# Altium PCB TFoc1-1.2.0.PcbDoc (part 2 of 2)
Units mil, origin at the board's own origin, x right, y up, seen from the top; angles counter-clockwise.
Board outline 1584.83 x 1584.83 mil, 4 copper layers (Top Layer, GND, SIGNAL, Bottom Layer), stack 61.85 mil thick; 89 components, 88 nets, 364 pads, 205 vias.
Unrouted connection lines stored in the file: 1.
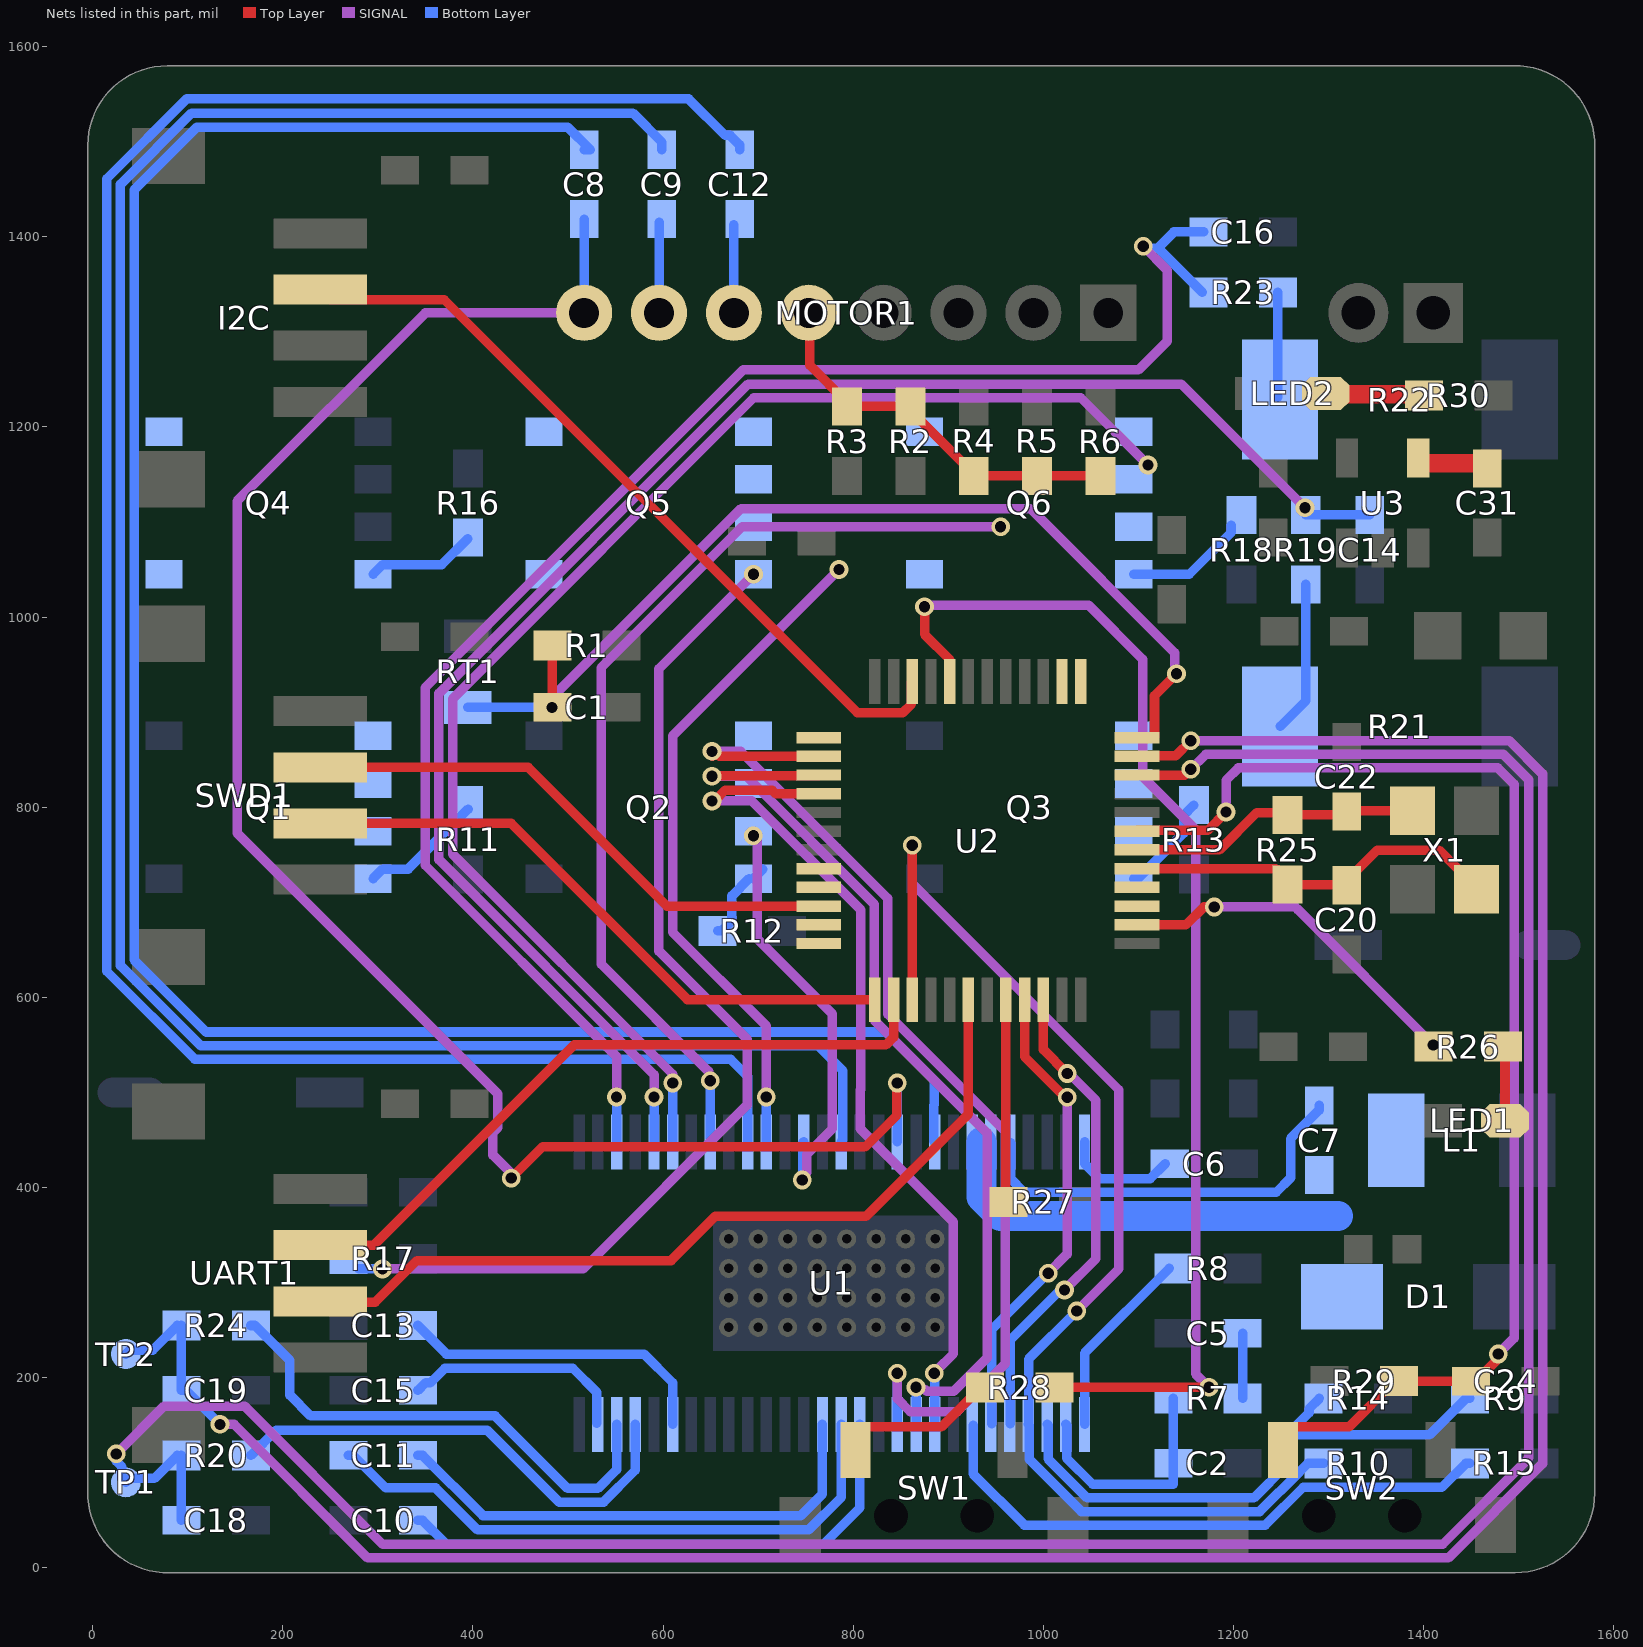
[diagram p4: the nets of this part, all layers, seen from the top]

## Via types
v1: diameter 19.68, hole 11.81, Top Layer to Bottom Layer, tented both sides, 205 vias

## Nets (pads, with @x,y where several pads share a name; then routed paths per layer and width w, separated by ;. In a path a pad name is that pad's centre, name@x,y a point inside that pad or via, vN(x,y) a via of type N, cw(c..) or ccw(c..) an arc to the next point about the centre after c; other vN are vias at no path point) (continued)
I2C_SDA: I2C.2 U2.22 | length 832.7
  Top Layer w10: I2C.2@239.45,1344.53 250.2,1333.78 369.9,1333.78 804.19,899.49 852.29,899.49 861.11,908.31 U2.22@861.11,931.32
M_A: C8.1 MOTOR1.8 Q1.S Q4.D U1.46 | length 1902.9
  Top Layer w10: v1(440.31,410) 473.31,443 812.73,443 845.89,476.15 845.89,509.49 v1(846.4,510)
  SIGNAL w10: v1@440,415.42 421.14,434.28 421.14,457.94 425.98,462.78 425.98,498.86 152.01,772.83 152.01,1122.01 350,1320 MOTOR1.8@515.37,1320
  Bottom Layer w10: MOTOR1.8@517.01,1320 517.01,1418.23 C8.1@517.27,1418.5 ; U1.46@846.4,448 v1(846.4,510)
M_B: C9.1 MOTOR1.7 Q2.S Q5.D U1.41 | length 542.8
  SIGNAL w10: v1(695,770) 699.25,765.75 699.25,661.55 778.02,582.78 778.02,461.89 751.13,435 751.13,415.42 747.52,411.81 v1@747.52,409.19
  Bottom Layer w10: MOTOR1.7@595.75,1320 C9.1@595.75,1415.4 ; v1@747.13,408.8 747.13,447.16 U1.41@747.97,448
  other v1: 746.28,407.95
M_B_Current: Q5.S R19.1 R21.2 U1.39 | length 875.9
  SIGNAL w10: v1(708.6,495.29) 708.6,570 610,668.6 610,875 v1(785,1050)
  Bottom Layer w10: U1.39@708.6,448 v1(708.6,495.29) ; R21.2@1249.02,885 1275.92,911.9 R19.1@1275.92,1034.44
M_C: C12.1 MOTOR1.6 Q3.S Q6.D U1.36 | length 1120.3
  SIGNAL w10: v1(649.55,512.29) 647.87,513.97 647.87,522.13 535,635 535,946.87 683.13,1095 v1(955,1095)
  Bottom Layer w10: U1.36@649.55,448 v1(649.55,512.29) ; MOTOR1.6@674.49,1320 C12.1@674.49,1412.58
M_C_Current: Q6.S R22.2 R23.1 U1.34 | length 1563.8
  SIGNAL w10: v1(610.18,510) 610.18,519.29 378.63,750.84 378.63,913.9 695.4,1230.67 1039.33,1230.67 v1(1110,1160)
  Bottom Layer w10: U1.34@610.18,448 v1(610.18,510) ; R22.2@1246.52,1231.29 R23.1@1246.52,1341.39
MSPI_SCLK: U1.11 U2.26 | length 1125
  Top Layer w10: v1@651.42,854.17 v1@651.71,853.88 ; v1(651.42,858.79) 654.04,858.79 659.25,853.58 U2.26@763.1,853.58 ; U2.26@763.39,853.88 U2.26@763.69,853.58
  SIGNAL w10: v1(651.42,858.79) 681.74,858.79 836.33,704.2 836.33,582.41 960,458.74 960,215 909.33,164.33 860,164.33 846.4,177.93 v1(846.4,204.81)
  Bottom Layer w10: U1.11@846.4,151 v1(846.4,204.81)
MSPI_SDI: U1.9 U2.28 | length 908.5
  Top Layer w10: v1@652.98,805.55 654.6,803.92 v1@655.89,803.92 ; v1@654.6,807.26 665.18,817.83 714.81,817.83 718.44,814.21 U2.28@763.69,814.21
  SIGNAL w10: v1(651.42,806.69) 693.31,806.69 807.67,692.33 807.67,503.07 807.54,502.94 807.54,461.79 905.33,364 905.33,225.33 v1@887.58,207.58
  Bottom Layer w10: v1(885.26,204.81) 885.51,204.56 U1.9@885.51,151.26
MSPI_SDO: U1.10 U2.27 | length 996.2
  Top Layer w10: v1@651.42,830.16 652.01,829.57 v1@654.63,829.57 ; v1(651.42,832.74) 652,833.32 U2.27@763.11,833.32
  SIGNAL w10: v1(651.42,832.74) 687.53,832.74 822,698.27 822,576.47 940.85,457.62 940.85,220.85 905.64,185.64 877.31,185.64 874.81,188.15 867.94,188.15 v1@867.67,188.41
  Bottom Layer w10: U1.10@866.08,151 v1(866.08,190)
NetC2_1: C2.1 R7.1 U1.2 | length 249.8
  Bottom Layer w10: U1.2@1023.56,151 1024.56,150 1024.56,115.31 1051.88,87.99 1136.59,87.99 C2.1@1136.59,110 R7.1@1136.59,178.33
NetC5_1: C5.1 R7.2 | length 68.3
  Bottom Layer w10: R7.2@1209.59,178.33 C5.1@1209.59,246.67
NetC6_2: C6.2 U1.56 | length 120.4
  Bottom Layer w10: U1.56@1043.25,448 1043.25,425.22 1058.98,409.49 1112.38,409.49 C6.2@1127.89,425
NetC7_1: C7.1 D1.2 L1.1 U1.50 U1.51 | length 441.3
  Bottom Layer w31.5: 935,448 935,390 955,370 1310,370
NetC7_2: C7.2 U1.52 | length 432.9
  Bottom Layer w10: U1.52@965.51,447 965.51,409.49 979.92,395.08 1244.83,395.08 1260,410.25 1260,451.5 1290,481.5 C7.2@1290,486.5
NetC8_2: C8.2 U1.48 | length 2292.1
  Bottom Layer w10: C8.2@517.27,1491.5 523.5,1491.5 500,1515 109.49,1515 43.66,1449.17 43.66,639.49 119.49,563.66 834.22,563.66 885.26,512.63 885.26,487.06 884.77,486.57 884.77,449 U1.48@885.77,448
NetC9_2: C9.2 U1.43 | length 2324
  Bottom Layer w10: C9.2@598.84,1491.5 598.84,1499.43 568.28,1530 104.22,1530 29.33,1455.11 29.33,633.55 113.55,549.33 762.78,549.33 789.17,522.94 789.17,449.83 U1.43@787.34,448
NetC10_1: C10.1 U1.13 | length 578.7
  Bottom Layer w10: C10.1@342.18,50 347.18,50 372.18,25 768.68,25 807.03,63.35 U1.13@807.03,151
NetC11_1: C11.1 U1.14 | length 641.6
  Bottom Layer w10: C11.1@269.18,118.33 274.18,118.33 308.34,84.17 360.83,84.17 405,40 753.11,40 787.34,74.23 U1.14@787.34,151
NetC11_2: C11.2 U1.15 | length 534.4
  Bottom Layer w10: C11.2@342.18,118.33 347.18,118.33 410.51,55 745,55 767.66,77.66 U1.15@767.66,151
NetC12_2: C12.2 U1.38 | length 2347.5
  Bottom Layer w10: C12.2@680.41,1491.5 680.41,1496.5 670.41,1506.5 665.41,1506.5 626.91,1545 98.95,1545 15,1461.05 15,627.62 107.62,535 671,535 688.92,517.08 U1.38@688.92,448
NetC13_2: C13.2 U1.23 | length 336.8
  Bottom Layer w10: C13.2@342.18,255 372.18,225 580,225 610.18,194.82 U1.23@610.18,151
NetC14_2: C14.2 R19.2 U1.33 | length 1732.3
  SIGNAL w10: v1(590.49,495.29) 590.49,518.71 364.3,744.9 364.3,919.83 689.47,1245 1145,1245 v1(1275,1115)
  Bottom Layer w10: U1.33@590.49,448 v1(590.49,495.29) ; R19.2@1275.92,1107.44 C14.2@1343.42,1107.44
NetC15_1: C15.1 U1.27 | length 241
  Bottom Layer w10: C15.1@342.18,186.67 350.33,194.82 355.33,194.82 370.51,210 505,210 530.44,184.56 U1.27@530.44,152
NetC16_2: C16.2 R23.2 U1.31 | length 1739.7
  SIGNAL w10: v1(551.12,495.29) 551.12,537.81 349.97,738.96 349.97,925.77 684.2,1260 1100,1260 1130,1290 1130,1365 v1(1105,1390)
  Bottom Layer w10: U1.31@551.12,448 v1(551.12,495.29) ; v1(1105,1390) 1106.85,1388.15 1120.47,1388.15 ; R23.2@1167.23,1341.39 1120.47,1388.15 ; C16.2@1168.52,1405 1137.32,1405 1120.47,1388.15
NetC31_1: C31.1 U3.4 | length 69.6
  Top Layer w19.68: U3.4@1399.47,1161.87 1461.54,1161.87 1466.69,1156.71 C31.1@1466.69,1156.5
NetLED1_2: LED1.2 R26.2 | length 72.7
  Top Layer w10: LED1.2@1485.44,480.26 R26.2@1485.44,553
NetLED2_2: LED2.2 R30.1 | length 102.9
  Top Layer w19.68: LED2.2@1296.7,1235.26 1297.7,1234.26 R30.1@1399.19,1234.26
NetMOTOR1_5: MOTOR1.5 R2.2 R3.2 R4.1 R5.1 R6.1 | length 417.2
  Top Layer w10: MOTOR1.5@754.27,1318.96 754.27,1265 793.52,1225.75 R3.2@793.52,1221.5 R2.2@860.14,1221.5 860.14,1217.25 913.89,1163.5 916.01,1163.5 R4.1@931.01,1148.5 ; R4.1@926.76,1148.5 R4.1@931.01,1148.5 ; R6.1@1060,1148.5 R5.1@993.38,1148.5 R4.1@931.01,1148.5
NetQ1_G: Q1.G R11.1 | length 130.3
  Bottom Layer w10: Q1.G@295.04,725 305.04,735 331.87,735 R11.1@395,798.13
NetQ2_G: Q2.G R12.1 | length 85.4
  Bottom Layer w10: R12.1@657.35,670 661.6,670 672.35,680.75 672.35,706.81 Q2.G@690.54,725 ; Q2.G@695.04,725 Q2.G@705.04,735
NetQ3_G: Q3.G R13.1 | length 106
  Bottom Layer w10: Q3.G@1095.04,725 1099.54,725 1147.39,772.85 1147.39,791.47 R13.1@1158.14,802.22
NetQ4_G: Q4.G R16.1 | length 115.3
  Bottom Layer w10: Q4.G@295.04,1045 305.04,1055 367.12,1055 R16.1@394.72,1082.6
NetQ5_G: Q5.G R17.1 | length 1117.7
  SIGNAL w10: v1(305,314.43) 516.01,314.43 688.29,486.71 688.29,556.18 595.67,648.8 595.67,945.63 v1(695.04,1045)
  Bottom Layer w10: R17.1@279.74,314.43 v1(305,314.43)
NetQ6_G: Q6.G R18.1 | length 128.4
  Bottom Layer w10: Q6.G@1095.04,1045 1153.38,1045 1197.67,1089.29 R18.1@1197.67,1096.69
NetR8_2: R8.2 U1.1 | length 200.9
  Bottom Layer w10: U1.1@1043.25,151 1043.25,225.91 R8.2@1132.33,315
NetR9_2: R9.2 R14.1 U1.3 | length 611.6
  Bottom Layer w10: U1.3@1003.88,151 1004.88,150 1004.88,114.73 1045.95,73.66 1221.44,73.66 1255.34,107.55 1255.34,139.1 1256.23,140 ; R14.1@1290.31,178.33 1279.57,167.59 1279.57,163.33 1256.23,140 ; R9.2@1448.5,178.33 1444.25,178.33 1405.91,140 1256.23,140
NetR15_2: R15.2 U1.7 | length 622.7
  Bottom Layer w10: U1.7@926.14,150 926.14,98.86 980,45 1233.31,45 1273.24,84.92 1419.17,84.92 1444.25,110 R15.2@1448.5,110
NetR20_2: R20.2 U1.25 | length 508.8
  Bottom Layer w10: R20.2@166.5,118.33 193.17,145 415,145 490.67,69.33 537.38,69.33 570.81,102.76 U1.25@570.81,151
NetR24_2: R24.2 U1.26 | length 532.7
  Bottom Layer w10: R24.2@166.5,255 170.75,255 207.52,218.23 207.52,181.83 229.35,160 423.33,160 499.67,83.66 531.44,83.66 551.12,103.34 U1.26@551.12,151
NetR27_2: R27.2 U2.44 | length 209.7
  Top Layer w10: R27.2@960.54,387.96 960.54,525 U2.44@960.54,597.68
NetR28_1: R28.1 SW1.2 | length 167.4
  Top Layer w10: SW1.2@802.32,123.9 802.32,137.68 813.07,148.43 892.67,148.43 R28.1@934.25,190
NetU2_3: U2.3
NetU2_4: U2.4
NetU2_13: U2.13
NetU2_14: U2.14
NetU2_25: U2.25
NetU2_32: U2.32
NetU2_33: U2.33
NetU2_35: U2.35
NetU2_36: U2.36
nFAULT: U1.6 U2.45 | length 498.4
  Top Layer w10: U2.45@980.22,597.68 980.22,537.66 1022.89,495 v1(1025,495)
  SIGNAL w10: v1(1005,310) 1025,330 v1(1025,495)
  Bottom Layer w10: U1.6@945.72,151.89 945.72,250.72 v1(1005,310)
nOCTW: U1.5 U2.46 | length 508
  Top Layer w10: U2.46@999.91,597.68 999.91,545.09 v1(1025,520)
  SIGNAL w10: v1(1022.25,292.25) 1055,325 1055,492.11 v1@1027.11,520
  Bottom Layer w10: U1.5@965.01,151.5 965.01,239.5 1017.75,292.25 v1(1022.25,292.25)
NRST: C24.2 R29.1 SW2.2 U2.7 | length 1331.8
  Top Layer w10: U2.7@1098.33,774.84 1099.33,775.84 1172.91,775.84 v1(1192.07,795) ; SW2.2@1252.05,123.9 1252.05,137.68 1262.8,148.43 1321.51,148.43 R29.1@1369.5,196.42 ; R29.1@1373.76,196.42 C24.2@1449.69,196.42 1454.69,196.42 1476.42,218.15 1476.42,223.15 v1(1478.27,225)
  SIGNAL w10: v1(1192.07,795) 1192.07,828.43 1204.98,841.34 1477.82,841.34 1495,824.16 1495,241.73 v1(1478.27,225)
OSC_IN: C20.1 R25.1 U2.5 X1.3 | length 406.8
  Top Layer w10: U2.5@1098.33,735.47 1244.57,735.47 1251.5,728.54 R25.1@1251.5,713.66 ; R25.1@1256.82,718.5 C20.1@1314.56,718.5 ; C20.1@1318.56,718.5 C20.1@1314.56,718.5 ; X1.3@1455.28,713.66 1455.28,715.63 1415.91,755 1351.06,755 C20.1@1314.56,718.5
OSC_OUT: C22.1 R25.2 U2.6 X1.1 | length 308.3
  Top Layer w10: U2.6@1099.33,756.16 1100.33,755.16 1185.16,755.16 1224.17,794.17 1254.61,794.17 R25.2@1256.82,791.97 1315.53,791.97 C22.1@1319.06,795.51 1319.89,796.34 X1.1@1388.35,796.34
PB2: R28.2 U2.20 | length 1300.2
  Top Layer w10: v1(875,1011) 875,981.81 901.48,955.33 U2.20@901.48,932.32 ; R28.2@1011.5,190 v1(1174.17,190)
  SIGNAL w10: v1(875,1011) 876.24,1012.24 1047.76,1012.24 1104.33,955.67 1104.33,832.36 1160,776.69 1160,204.17 v1(1174.17,190)
PC13: R26.1 U2.2 | length 379.6
  Top Layer w10: U2.2@1098.33,676.42 1149.92,676.42 1168.71,695.21 v1(1179.64,695.21)
  SIGNAL w10: v1(1179.64,695.21) 1264.79,695.21 1267.67,692.33 v1(1410,550)
PWRGD: R10.2 U1.4 U2.39 | length 1290.8
  Top Layer w10: U2.39@862.11,597.68 v1(862.11,760)
  SIGNAL w10: v1(862.11,760) 862.11,720 1079.17,502.94 1079.17,314.43 v1(1035,270.26)
  Bottom Layer w10: U1.4@984.19,151 985.19,150 985.19,114.15 1040.01,59.33 1227.38,59.33 1269.67,101.62 1269.67,101.71 1277.95,110 R10.2@1294.57,110 ; U1.4@984.33,151.14 984.33,219.6 v1(1035,270.26)
SO1: C18.1 R20.1 TP1.1 U2.10 | length 2912.4
  Top Layer w10: U2.10@1098.33,833.9 1148.9,833.9 v1(1155,840)
  SIGNAL w10: v1(25,120) 75.17,170.17 159.83,170.17 305,25 1420,25 1510.67,115.67 1510.67,828.76 1483.76,855.67 1170.67,855.67 v1(1155,840)
  Bottom Layer w10: v1(25,120) 25,112.38 30.89,106.49 TP1.1@30.89,94.11 ; TP1.1@35,90 39.11,94.11 65.03,94.11 R20.1@89.25,118.33 ; C18.1@93.5,50 R20.1@93.5,118.33
SO2: C19.1 R24.1 TP2.1 U2.11 | length 2853.8
  Top Layer w10: U2.11@1098.33,853.58 1099.04,854.29 1139.29,854.29 v1(1155,870)
  SIGNAL w10: v1(133.96,151) 149,151 289.33,10.67 1425.94,10.67 1525,109.73 1525,835 1490,870 v1(1155,870)
  Bottom Layer w10: TP2.1@35,225 39.11,229.11 63.36,229.11 R24.1@89.25,255 ; R24.1@93.5,255 C19.1@93.5,186.67 98.5,186.67 133.96,151.2 v1(133.96,151)
SWDCLK: SWD1.3 U2.37 | length 660
  Top Layer w10: SWD1.3@239.45,782.97 440.31,782.97 625.6,597.68 U2.37@822.74,597.68
SWDIO: SWD1.2 U2.34 | length 584.7
  Top Layer w10: SWD1.2@239.45,842.03 457.97,842.03 603.9,696.1 U2.34@763.69,696.1
TEMP: C1.1 R1.1 RT1.1 U2.12 | length 1078.8
  Top Layer w10: C1.1@483.5,905 R1.1@483.5,970 ; U2.12@1098.33,873.27 1115.83,873.27 1116.83,874.27 1116.83,917.31 v1(1140,940.47)
  SIGNAL w10: v1@484.93,906.79 484.93,917.06 682.03,1114.17 986.36,1114.17 1138.15,962.39 1138.15,942.33 v1(1140,940.47)
  Bottom Layer w10: RT1.1@394.75,904.94 v1(483.07,904.94)
USART1_RX: U2.38 UART1.2 | length 733.1
  Top Layer w10: UART1.2@239.45,339.53 295.97,339.53 506.44,550 834.33,550 842.43,558.1 U2.38@842.43,597.68
USART1_TX: U2.42 UART1.3 | length 884.5
  Top Layer w10: UART1.3@239.45,280.47 240.45,279.47 297.15,279.47 341.03,323.35 608.35,323.35 655,370 813.89,370 921.17,477.28 U2.42@921.17,597.68
pads on no net: I2C.0 SW1.0 SW2.0 SWD1.0 U1.55 U1.V UART1.0 X1.2 X1.4
copper on no net: | length 62
  Bottom Layer w15: 681,358 712,358 743,358

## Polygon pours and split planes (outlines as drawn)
DGND on Top Layer "DGND_L01_P000" (solid, remove dead copper, pour order 0): 1500,1570 cw(c1500,1500) 1570,1500 1570,80 cw(c1495,80) 1495,5 80,5 cw(c80,80) 5,80 5,1500 cw(c75,1500) 75,1570
DGND on SIGNAL "DGND_L03_P006" (solid, remove dead copper, pour order 6): 1485,1575 cw(c1485,1485) 1575,1485 1575,90 cw(c1485,90) 1485,0 99.14,0 cw(c99.14,94.14) 5,94.14 5,1500 cw(c80,1500) 80,1575
DCBUS on Bottom Layer "DCBUS_L04_P010" (solid, remove dead copper, pour order 10): 59.18,740 59.18,648.8 135.75,572.22 301.72,572.22 305.73,640.06 302.8,642.98 275.79,670 245.99,670 245.99,701.24 235.45,711.78 235.45,740
DCBUS on Bottom Layer "DCBUS_L04_P008" (solid, remove dead copper, pour order 8): 457.28,740 621.24,740 621.24,600 616.24,605 455,605
GND on GND (split plane): 1560.63,1549.94 1563.18,1546.25 1560.32,1549.98 1557.39,1553.18
GND on GND (split plane): 1569.24,1537.51 1571.03,1533.54 1568.71,1538.01 1566.59,1541.33
GND on GND (split plane): 1549.94,1560.63 1553.18,1557.39 1549.98,1560.32 1546.25,1563.18
GND on GND (split plane): 1579.15,1509.06 1579.41,1505.03 1578.67,1510.63 1578.04,1513.51
GND on GND (split plane): 1575.48,1523.73 1576.5,1519.65 1574.89,1524.75 1573.55,1527.98
GND on GND (split plane): 1509.07,1579.15 1513.51,1578.04 1510.63,1578.67 1505.03,1579.41
GND on GND (split plane): 71.43,1579.63 65.84,1578.89 70.49,1579.82 75.77,1579.82
GND on GND (split plane): 1537.51,1569.24 1541.33,1566.59 1538.01,1568.71 1533.54,1571.03
GND on GND (split plane): 1523.73,1575.48 1527.98,1573.55 1524.75,1574.89 1519.65,1576.5
GND on GND (split plane): 1579.82,70.49 1578.89,65.84 1579.63,71.43 1579.82,75.77
GND on GND (split plane): 1576.6,54.31 1575.06,50.6 1577.09,57.03 1577.58,59.26
GND on GND (split plane): 1570.29,39.07 1567.48,34.87 1568.71,36.8 1571.82,42.78
GND on GND (split plane): 1561.12,25.35 1557.39,21.62 1560.32,24.82 1563.75,29.29
GND on GND (split plane): 1549.45,13.68 1545.51,11.05 1549.98,14.48 1553.18,17.41
GND on GND (split plane): 1535.74,4.52 1532.02,2.98 1538.01,6.09 1539.93,7.32
GND on GND (split plane): 1520.49,-1.8 1515.54,-2.78 1517.77,-2.29 1524.21,-0.26
GND on GND (split plane): 1504.31,-5.01 1499.04,-5.01 1503.37,-4.83 1508.96,-4.09
GND on GND (split plane): 57.03,1577.09 50.6,1575.06 54.31,1576.6 59.26,1577.58
GND on GND (split plane): 36.8,1568.71 34.87,1567.48 39.07,1570.29 42.78,1571.82
GND on GND (split plane): 24.82,1560.32 21.62,1557.39 25.35,1561.12 29.29,1563.76
GND on GND (split plane): 14.48,1549.98 11.05,1545.51 13.68,1549.45 17.41,1553.19
GND on GND (split plane): 6.09,1538.01 2.98,1532.02 4.52,1535.74 7.32,1539.93
GND on GND (split plane): -2.29,1517.77 -2.78,1515.54 -1.8,1520.49 -0.26,1524.21
GND on GND (split plane): -3.87,64.17 -3.36,61.85 -4.42,66.19 -4.65,70.1
GND on GND (split plane): -4.83,1503.37 -5.02,1499.04 -5.02,1504.31 -4.09,1508.96
GND on GND (split plane): 36.8,6.09 41.42,3.68 37.46,5.46 33.57,8.15
GND on GND (split plane): 78.77,1579.76 1500.2,1579.76 1501.48,1579.51 1501.51,1579.59 1501.52,1579.59 1501.51,1579.51 1503.36,1579.43 1510.59,1578.48 1517.72,1576.9 1524.68,1574.7 1531.43,1571.91 1537.91,1568.54 1544.06,1564.61 1549.85,1560.17 1555.24,1555.24 1560.17,1549.85 1564.61,1544.06 1568.54,1537.91 1571.91,1531.43 1574.7,1524.68 1576.9,1517.72 1578.48,1510.59 1579.43,1503.36 1579.51,1501.51 1579.59,1501.52 1579.59,1501.51 1579.51,1501.48 1579.76,1500.2 1579.76,78.74 1579.75,78.74 1579.43,71.45 1578.48,64.21 1576.9,57.08 1574.7,50.12 1571.91,43.37 1568.54,36.9 1564.61,30.74 1560.17,24.95 1555.24,19.57 1549.85,14.63 1544.06,10.19 1537.91,6.27 1531.43,2.9 1524.68,0.1 1517.72,-2.09 1510.59,-3.67 1503.36,-4.63 1496.06,-4.94 1496.06,-4.96 75,-4.96 73.83,-4.73 73.81,-4.82 73.8,-4.82 73.81,-4.73 71.45,-4.63 64.21,-3.67 57.08,-2.09 50.12,0.1 43.37,2.9 36.9,6.27 30.74,10.19 24.95,14.63 19.57,19.57 14.63,24.95 10.19,30.74 6.27,36.9 2.9,43.37 0.1,50.12 -2.09,57.08 -3.67,64.21 -4.63,71.45 -4.73,73.81 -4.82,73.8 -4.82,73.81 -4.73,73.83 -4.96,75 -4.96,1496.06 -4.94,1496.06 -4.63,1503.36 -3.67,1510.59 -2.09,1517.72 0.1,1524.68 2.9,1531.43 6.27,1537.91 10.19,1544.06 14.63,1549.85 19.57,1555.24 24.95,1560.17 30.74,1564.61 36.9,1568.54 43.37,1571.91 50.12,1574.7 57.08,1576.9 64.21,1578.48 71.45,1579.43 78.74,1579.75 78.74,1579.76 78.77,1579.76
GND on GND (split plane): 64.17,-3.87 70.1,-4.65 66.19,-4.42 61.85,-3.36
GND on GND (split plane): 50.05,-0.09 55.4,-1.77 51.38,-0.78 47.09,1.14
GND on GND (split plane): 6.09,36.8 8.15,33.57 5.46,37.46 3.68,41.42
GND on GND (split plane): -0.09,50.05 1.14,47.09 -0.79,51.38 -1.77,55.4
GND on GND (split plane): 24.82,14.48 28.63,11.56 24.91,14.12 21.62,17.41
GND on GND (split plane): 14.48,24.82 17.41,21.62 14.12,24.91 11.56,28.63

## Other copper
SIGNAL:
  region net DCBUS: 905.33,720 1050.94,565 ccw(c1056.97,571.04) 1056.97,562.5 1085,562.5 ccw(c1085,567.5) 1090,567.5 1090,600 945,760 ccw(c940.92,755.92) 940.92,761.69 909.41,761.69 ccw(c909.41,755.92) 905.33,760 ccw(c913.45,751.88) 901.97,751.88 901.97,728.12 ccw(c913.45,728.12)
  region net DCBUS: 225,455 185.85,455 cw(c185.85,465.85) 175,465.85 175,510 80,715 80,767.17 cw(c92.83,767.17) 92.83,780 120,780 cw(c120,770) 130,770 130,727.56 225,510
  region: 225,455.96
Bottom Layer:
  rectangle net DCBUS: 81.15,711.25 180,785
  rectangle net GND: 248.91,1078.45 349.61,1211.49
  rectangle net NetC7_1: 920,420 950,475
  region net GND: 1460,821.32 1460,1365 ccw(c1436.85,1365) 1436.85,1388.15 1388.15,1388.15 ccw(c1388.15,1360) 1360,1360 1363.89,1308.62 cw(c1337.2,1315.82) 1330,1289.13 cw(c1323.62,1325.75) 1287.14,1318.63 1283.12,1455.16 cw(c1341.78,1456.89) 1350,1515 1460,1515 cw(c1460,1430) 1545,1430 1545,826.32 cw(c1540,826.32) 1540,821.32
  region net DCBUS: 175,520 174.3,519.3 174.3,460 ccw(c179.3,460) 179.3,455 265,455 ccw(c265,475) 285,475 285,515 ccw(c280,515) 280,520
  region net M_C: 906.46,1030.07 ccw(c1021.52,1030.07) 1021.52,915 cw(c1021.52,881.52) 1055,881.52 ccw(c1063.98,881.52) 1063.98,872.54 1106.85,872.54 ccw(c1106.85,879.12) 1113.43,879.12 1113.43,961.52 ccw(c1068.97,961.52) 1068.97,1005.98 1060.23,1005.98 cw(c1060.23,1028.99) 1037.23,1028.99 1037.23,1030
  region net M_B_Current: 675.74,1210 675.74,1080.2 719.26,1080.2 cw(c719.54,1037.74) 762,1038 762,691 ccw(c808,691) 808,645 875,645 cw(c875.01,615.09) 886.46,642.72 ccw(c953.53,710.02) 953.52,615 1187.03,615 ccw(c1187.03,717.42) 1289.45,717.42 1289.45,925.22 ccw(c1269.67,925.22) 1269.67,945 1246.4,945 ccw(c1241.94,913.4) 1210.34,917.84 1208.04,729.39 cw(c1162.38,720.67) 1171.08,675 1010,675 927.5,705 856.4,705 cw(c856.4,715) 846.4,715 846.4,1147.6 ccw(c824,1147.61) 824,1170 774.2,1170 cw(c774.2,1190) 754.2,1190 ccw(c734.21,1190) 734.2,1210
  region net NetC7_1: 1271.99,250 1355,250 1355,325 cw(c1375,325) 1375,345 ccw(c1375,370) 1400,370 1400,405 ccw(c1370,405) 1370,435 1283.97,435 ccw(c1283.97,423.02) 1271.99,423.02
  region net M_C: 672.52,1349.45 cw(c672.56,1322.01) 700,1322.05 700,1308.62 ccw(c770.91,1379.54) 770.91,1279.25 967.98,1279.25 cw(c967.98,1210) 1037.23,1210 cw(c1008.19,1210) 1008.19,1180.97 840.46,1180.97 cw(c840.45,1280.96) 778.22,1202.69 ccw(c725.98,1126.4) 708.95,1217.28 cw(c717.35,1292.11) 645,1271.24 645,1321.93 cw(c672.52,1321.93)
  region net M_C_Current: 1075,1213.51 cw(c1085,1213.51) 1085,1223.51 1108.44,1223.51 ccw(c1108.44,1283.57) 1168.5,1283.57 cw(c1176.36,1283.57) 1176.36,1291.43 1243.5,1291.43 cw(c1243.5,1274.93) 1260,1274.93 1260,1189.47 cw(c1237.03,1189.47) 1237.03,1166.5 1210,1166.5 ccw(c1210,1126.5) 1170,1126.5 1168.5,1075 cw(c1162.22,1076.28) 1160.94,1070 1142.94,1070 1105,1070 cw(c1102.31,1111.31) 1075,1080.2 cw(c1086.83,1085.1) 1075,1090
  region net M_B: 456.1,1034.95 ccw(c555.08,1032.52) 552.65,933.54 593.69,933.54 cw(c593.69,860.08) 667.15,860.08 667.15,765.72 ccw(c677.87,765.72) 677.87,755 746.65,755 ccw(c746.65,762.55) 754.2,762.55 754.2,880.89 ccw(c654.2,880.89) 695.06,972.16 cw(c695.06,1030) 637.23,1030
  region net M_A: 330.05,760 330.05,904.94 ccw(c216.1,916.77) 301.72,992.89 242.26,1017.44 cw(c269.19,1037.18) 235.8,1037.18 ccw(c218.52,1030.03) 231.73,1043.27 225,1050 ccw(c200.87,1025.88) 200.86,1060 67.07,1060 ccw(c67.06,1042.95) 55,1055 55,1003.5 ccw(c109.86,1003.5) 71.07,964.71 86.84,948.94 ccw(c147.63,1009.73) 147.63,923.76 206.91,923.76 cw(c206.92,859.73) 252.19,905 cw(c197.15,849.95) 275,849.94 275,760
  region net M_B: 593.78,1350 cw(c594.39,1319.39) 625,1319.97 630.82,1244.92 cw(c580.54,1217.22) 637.23,1226.27 637.23,1210 cw(c577.23,1210) 577.23,1150 485,1150 cw(c485,1180) 455,1180 455,1210 cw(c470,1210) 470,1225 520,1225 ccw(c517.5,1267.5) 560,1270 565,1321.22 cw(c593.78,1321.22)
  region net M_A: 79.23,1200 79.23,1250.06 cw(c179.23,1250.06) 179.23,1350.06 520,1350.06 cw(c520.04,1323.71) 546.39,1323.61 546.39,1320 cw(c469.2,1320) 469.2,1242.8 270.03,1242.8 ccw(c270.03,1210) 238.79,1200
  region net M_C: 1114.33,890 1114.33,765.89 cw(c1108.44,765.89) 1108.44,760 1060.66,760 cw(c1060.66,765.66) 1055,765.66 1055,881.52 cw(c1063.48,881.52) 1063.48,890
  region: 248.91,1211.49
  region net M_C: 930.28,1030.07
  region: 980,505
  region net M_A: 275,760
  region: 557.53,1445.74

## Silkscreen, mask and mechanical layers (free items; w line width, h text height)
Top Overlay:
  lines w10: 1175,935 1175,1280 1550,1280 1550,935 1175,935 ; 1200,605 1515,605 1515,920 1200,920 1200,605
  text "I2C" at 130,1505 h60
  text "VCC+" at 1500,1425 h60 r270
  text "20250424 / TFoc1-1.2.0" at 320,1150 h60
  text "SWD" at 130,995 h60
  text "UART" at 130,500 h60
  text "3.3V" at 1230,450 h60
  text "DGND" at 1158.44,315 h60
  text "PGND" at 1433.44,315 h60
  text "RST" at 1158.44,175 h60
  text "PB2" at 785,170 h60
Bottom Overlay:
  region: 1380,80 1380,210 1400,145
  text "SO2" at 50,310 h39.37 r90
  text "SO1" at 50,180 h39.37 r90
Bottom Paste:
  region: 515,1355
Bottom Solder:
  region: 1075,1213.51 cw(c1085,1213.51) 1085,1223.51 1108.44,1223.51 ccw(c1108.44,1283.57) 1168.5,1283.57 cw(c1176.36,1283.57) 1176.36,1291.43 1243.5,1291.43 cw(c1243.5,1274.93) 1260,1274.93 1260,1189.47 cw(c1237.03,1189.47) 1237.03,1166.5 1210,1166.5 ccw(c1210,1126.5) 1170,1126.5 1168.5,1075 cw(c1162.22,1076.28) 1160.94,1070 1142.94,1070 1105,1070 cw(c1102.31,1111.31) 1075,1080.2 cw(c1086.83,1085.1) 1075,1090
  region: 672.52,1349.45 cw(c672.56,1322.01) 700,1322.05 700,1308.62 ccw(c770.91,1379.54) 770.91,1279.25 967.98,1279.25 cw(c967.98,1210) 1037.23,1210 cw(c1008.19,1210) 1008.19,1180.97 840.46,1180.97 cw(c840.45,1280.96) 778.22,1202.69 ccw(c725.98,1126.4) 708.95,1217.28 cw(c717.35,1292.11) 645,1271.24 645,1321.93 cw(c672.52,1321.93)
  region: 593.78,1350 cw(c594.39,1319.39) 625,1319.97 630.82,1244.92 cw(c580.6,1217.24) 637.23,1226.27 cw(c612.21,1231.08) 607.4,1206.06 455.52,1206.07 cw(c470,1210) 470,1225 520,1225 ccw(c517.5,1267.5) 560,1270 565,1321.22 cw(c593.78,1321.22)
  region: 79.23,1206.06 79.23,1250.06 cw(c179.23,1250.06) 179.23,1350.06 520,1350.06 cw(c520.04,1323.71) 546.39,1323.61 546.39,1320 cw(c469.2,1320) 469.2,1242.8 270.03,1242.8 ccw(c270.03,1210) 237.47,1206.06
  region: 330.05,760 330.05,904.94 ccw(c216.1,916.77) 301.72,992.89 242.26,1017.44 cw(c269.19,1037.18) 235.8,1037.18 ccw(c218.53,1030.04) 231.73,1043.27 225,1050 ccw(c200.87,1025.88) 200.87,1060 67.22,1060 ccw(c67.06,1042.95) 55,1055 55,1003.5 ccw(c109.86,1003.5) 71.07,964.71 86.84,948.94 ccw(c147.63,1009.73) 147.63,923.76 206.91,923.76 cw(c206.92,859.74) 252.19,905 cw(c197.16,849.95) 275,849.94 275,760
Mechanical 1:
  lines w10: 0,75 0,1496.06 cw(c78.74,1496.06) 78.74,1574.8 1500.2,1574.8 ; 0,78.74 ccw(c78.74,78.74) 78.74,0 ; 75,0 1496.06,0 ccw(c1496.06,78.74) 1574.8,78.74 1574.8,1500.2 ; 1496.06,1574.8 cw(c1496.06,1496.06) 1574.8,1496.06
